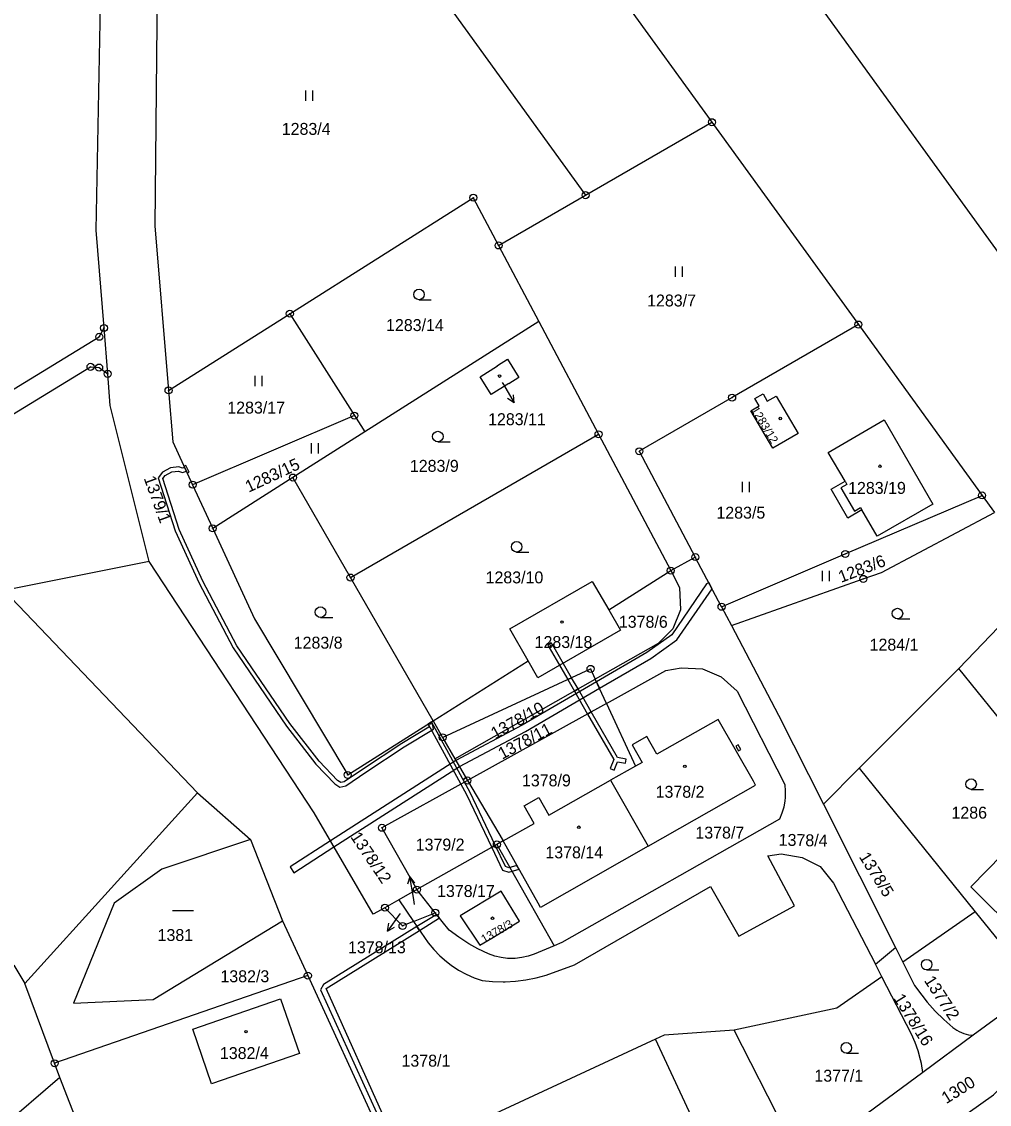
# Model space of a CAD drawing. Extents: x -562167 to -556918, y -1077891 to -1070763.
# Drawn here: x -559666.6 to -559528.9, y -1075327 to -1075172.9 of the extents above; entities that cross this region are included whole.
import ezdxf

# ---------------------------------------------------------------- set-up
doc = ezdxf.new("R2010")
doc.units = 0
for name, color, linetype in [('Hranice parcel', 7, 'Continuous'), ('Parcelní čísla', 7, 'Continuous'), ('Pop  PČ popisy', 7, 'Continuous'), ('Vnitřní kresba', 7, 'Continuous'), ('Věcná břemena k části', 7, 'Continuous'), ('Značky bodu BP', 7, 'Continuous'), ('Značky budov', 7, 'Continuous'), ('Značky kultur', 7, 'Continuous')]:
    doc.layers.add(name, color=color, linetype=linetype)

msp = doc.modelspace()

# ---------------------------------------------------------------- linework, layer by layer
at = {"layer": 'Hranice parcel'}
for p, q in [((-559616.74, -1075082.7), (-559508.88, -1075231.78)), ((-559633.14, -1075097.77), (-559568.42, -1075187.21)), ((-559648.43, -1075111.82), (-559586.39, -1075197.59)), ((-559586.39, -1075197.59), (-559568.42, -1075187.21)), ((-559568.42, -1075187.21), (-559547.57, -1075216)), ((-559598.77, -1075204.75), (-559586.39, -1075197.59)), ((-559598.77, -1075204.75), (-559593.03, -1075215.59)), ((-559645.74, -1075225.37), (-559628.48, -1075214.46)), ((-559628.48, -1075214.46), (-559619.3, -1075228.96)), ((-559654.4, -1075223.02), (-559654.92, -1075216.49)), ((-559593.03, -1075215.59), (-559617.83, -1075231.29)), ((-559593.03, -1075215.59), (-559584.55, -1075231.61)), ((-559547.57, -1075216), (-559529.98, -1075240.31)), ((-559619.3, -1075228.96), (-559642.32, -1075238.79)), ((-559619.3, -1075228.96), (-559617.83, -1075231.29)), ((-559617.83, -1075231.29), (-559628.04, -1075237.77)), ((-559619.85, -1075252), (-559584.55, -1075231.61)), ((-559584.55, -1075231.61), (-559574.28, -1075251.02)), ((-559628.04, -1075237.77), (-559639.45, -1075245)), ((-559619.85, -1075252), (-559628.04, -1075237.77)), ((-559642.32, -1075238.79), (-559639.45, -1075245)), ((-559529.98, -1075240.31), (-559528.22, -1075242.75)), ((-559574.28, -1075251.02), (-559570.78, -1075249.09)), ((-559567.05, -1075256.16), (-559570.78, -1075249.09)), ((-559608.09, -1075272.4), (-559619.85, -1075252)), ((-559583.1, -1075256.6), (-559574.28, -1075251.02)), ((-559567.05, -1075256.16), (-559565.65, -1075258.82)), ((-559533.28, -1075264.93), (-559526.49, -1075257.87)), ((-559608.09, -1075272.4), (-559594.56, -1075263.85)), ((-559547.45, -1075279.14), (-559533.28, -1075264.93)), ((-559508.11, -1075296.23), (-559533.28, -1075264.93)), ((-559604.99, -1075277.78), (-559585.01, -1075266.46)), ((-559583.41, -1075269.93), (-559585.01, -1075266.46)), ((-559583.41, -1075269.93), (-559603.21, -1075280.88)), ((-559583.41, -1075269.93), (-559579.3, -1075278.83)), ((-559608.09, -1075272.4), (-559606.74, -1075274.74)), ((-559606.74, -1075274.74), (-559604.99, -1075277.78)), ((-559604.99, -1075277.78), (-559603.21, -1075280.88)), ((-559579.3, -1075278.83), (-559582.85, -1075280.84)), ((-559552.55, -1075284.27), (-559547.45, -1075279.14)), ((-559547.45, -1075279.14), (-559530.96, -1075299.57)), ((-559603.21, -1075280.88), (-559598.14, -1075289.48)), ((-559582.85, -1075280.84), (-559577.5, -1075290.24)), ((-559666.17, -1075309.79), (-559641.62, -1075282.66)), ((-559641.62, -1075282.66), (-559634.09, -1075289.26)), ((-559552.55, -1075284.27), (-559542.31, -1075304.63)), ((-559558.82, -1075286.4), (-559589.78, -1075303.95)), ((-559634.09, -1075289.26), (-559629.52, -1075300.84)), ((-559598.14, -1075289.48), (-559599.02, -1075289.98)), ((-559599.02, -1075289.98), (-559610.4, -1075296.41)), ((-559599.02, -1075289.98), (-559590.88, -1075304.41)), ((-559551.1, -1075295.51), (-559545.15, -1075307.02)), ((-559610.4, -1075296.41), (-559612.98, -1075297.86)), ((-559607.78, -1075299.69), (-559610.4, -1075296.41)), ((-559612.98, -1075297.86), (-559614.95, -1075298.98)), ((-559612.98, -1075297.86), (-559610.88, -1075300.95)), ((-559610.88, -1075300.95), (-559607.78, -1075299.69)), ((-559605.79, -1075302.19), (-559607.78, -1075299.69)), ((-559530.96, -1075299.57), (-559541.25, -1075306.74)), ((-559530.96, -1075299.57), (-559522.17, -1075310.46)), ((-559629.52, -1075300.84), (-559625.92, -1075308.65)), ((-559610.88, -1075300.95), (-559608.8, -1075304)), ((-559590.88, -1075304.41), (-559593.7, -1075305.58)), ((-559589.78, -1075303.95), (-559590.88, -1075304.41)), ((-559545.15, -1075307.02), (-559542.31, -1075304.63)), ((-559542.31, -1075304.63), (-559541.25, -1075306.74)), ((-559667.76, -1075307.16), (-559666.17, -1075309.79)), ((-559544.22, -1075308.82), (-559545.15, -1075307.02)), ((-559541.25, -1075306.74), (-559539.57, -1075310.07)), ((-559625.92, -1075308.65), (-559661.95, -1075321.12)), ((-559625.92, -1075308.65), (-559615.78, -1075330.68)), ((-559540.01, -1075316.97), (-559544.22, -1075308.82)), ((-559661.95, -1075321.12), (-559666.17, -1075309.79)), ((-559522.17, -1075310.46), (-559531.22, -1075317.14)), ((-559555.67, -1075335.15), (-559565.25, -1075316.42)), ((-559531.22, -1075317.14), (-559538.42, -1075322.44)), ((-559661.19, -1075323.16), (-559661.95, -1075321.12)), ((-559661.19, -1075323.16), (-559677.66, -1075337.18)), ((-559656.31, -1075335.73), (-559661.19, -1075323.16)), ((-559538.42, -1075322.44), (-559555.67, -1075335.15))]:
    msp.add_line(p, q, dxfattribs=at)
for points in [[(-559649.72, -1075112.97), (-559646.94, -1075125.05), (-559647.7, -1075201.95), (-559645.74, -1075225.37)], [(-559654.92, -1075216.49), (-559656.04, -1075202.55), (-559654.55, -1075126.06), (-559654.77, -1075125.28)], [(-559628.48, -1075214.46), (-559602.37, -1075197.95), (-559598.77, -1075204.75)], [(-559696.59, -1075242.74), (-559683.29, -1075234.63), (-559686.52, -1075229.31), (-559685.67, -1075228.79), (-559682.43, -1075234.11), (-559655.59, -1075217.74), (-559654.92, -1075216.49)], [(-559547.57, -1075216), (-559565.54, -1075226.4), (-559578.75, -1075234.03), (-559570.78, -1075249.09)], [(-559597.3, -1075224.44), (-559597.34, -1075224.38), (-559599.82, -1075225.94), (-559601.39, -1075223.42), (-559598.91, -1075221.86), (-559598.94, -1075221.82), (-559597.51, -1075220.95), (-559595.89, -1075223.55), (-559597.3, -1075224.44)], [(-559702.63, -1075249.94), (-559656.84, -1075222.02), (-559655.62, -1075222.12), (-559654.4, -1075223.02)], [(-559648.52, -1075249.71), (-559654.04, -1075227.54), (-559654.4, -1075223.02)], [(-559645.74, -1075225.37), (-559645.13, -1075232.7), (-559642.32, -1075238.79)], [(-559556.13, -1075231.49), (-559559.75, -1075233.59), (-559562.86, -1075228.26), (-559561.71, -1075227.58), (-559562.31, -1075226.53), (-559561.13, -1075225.84), (-559560.54, -1075226.89), (-559559.26, -1075226.17), (-559556.13, -1075231.49)], [(-559551.88, -1075234.19), (-559543.93, -1075229.55), (-559536.97, -1075241.54), (-559544.88, -1075246.13), (-559547.08, -1075242.39), (-559549.06, -1075243.55), (-559551.45, -1075239.42), (-559549.48, -1075238.29), (-559551.88, -1075234.19)], [(-559567.05, -1075256.16), (-559549.45, -1075248.64), (-559529.98, -1075240.31)], [(-559565.65, -1075258.82), (-559546.88, -1075252.19), (-559544.27, -1075251.27), (-559528.22, -1075242.75)], [(-559639.45, -1075245), (-559633.51, -1075257.87), (-559620.24, -1075280.09), (-559608.09, -1075272.4)], [(-559648.52, -1075249.71), (-559669.15, -1075253.85), (-559641.62, -1075282.66)], [(-559614.95, -1075298.98), (-559616.6, -1075299.91), (-559625.03, -1075285.5), (-559648.52, -1075249.71)], [(-559574.28, -1075251.02), (-559573.01, -1075253.41), (-559572.91, -1075256.59), (-559573.97, -1075259.32), (-559576.07, -1075261.39), (-559585.01, -1075266.46)], [(-559594.56, -1075263.85), (-559597.16, -1075259.28), (-559585.44, -1075252.56), (-559583.1, -1075256.6)], [(-559583.1, -1075256.6), (-559581.42, -1075259.5), (-559593.18, -1075266.26), (-559594.56, -1075263.85)], [(-559565.65, -1075258.82), (-559558.93, -1075271.57), (-559552.55, -1075284.27)], [(-559583.41, -1075269.93), (-559574.96, -1075265.25), (-559572.78, -1075264.84), (-559569.75, -1075265), (-559567.1, -1075266.12), (-559564.81, -1075268.18), (-559558.06, -1075281.47)], [(-559606.74, -1075274.74), (-559585.69, -1075265), (-559585.01, -1075266.46)], [(-559577.5, -1075290.24), (-559562.2, -1075281.56), (-559562.52, -1075280.99), (-559567.55, -1075272.2), (-559576.27, -1075277.12), (-559577.68, -1075274.62), (-559579.77, -1075275.8), (-559578.35, -1075278.3), (-559579.3, -1075278.83)], [(-559603.21, -1075280.88), (-559615.37, -1075287.61), (-559610.4, -1075296.41)], [(-559598.14, -1075289.48), (-559593.71, -1075286.98), (-559595.12, -1075284.47), (-559593.04, -1075283.3), (-559591.62, -1075285.8), (-559582.85, -1075280.84)], [(-559558.06, -1075281.47), (-559557.98, -1075282.39), (-559557.99, -1075283.31), (-559558.04, -1075283.76), (-559558.2, -1075284.67), (-559558.46, -1075285.55), (-559558.82, -1075286.4)], [(-559520.98, -1075301.56), (-559518.66, -1075299.22), (-559519.76, -1075298.13), (-559515.5, -1075293.83), (-559522.6, -1075286.84), (-559531.58, -1075296), (-559524.56, -1075302.97), (-559522.08, -1075300.47), (-559520.98, -1075301.56)], [(-559634.09, -1075289.26), (-559646.7, -1075293.52), (-559653.49, -1075298.36), (-559659.26, -1075312.57), (-559647.94, -1075312.04), (-559629.52, -1075300.84)], [(-559577.5, -1075290.24), (-559592.8, -1075298.93), (-559593.12, -1075298.36), (-559598.14, -1075289.48)], [(-559592.02, -1075308.59), (-559587.98, -1075307.1), (-559568.64, -1075295.96), (-559564.58, -1075303.01), (-559556.66, -1075298.73), (-559560.48, -1075291.62), (-559558.58, -1075291.32), (-559555.58, -1075291.86), (-559553, -1075293.12), (-559551.1, -1075295.51)], [(-559598.41, -1075296.62), (-559604.23, -1075300.13), (-559601.45, -1075304.31), (-559599.76, -1075303.3), (-559595.8, -1075300.92), (-559598.41, -1075296.62)], [(-559610.88, -1075300.95), (-559612.44, -1075301.58), (-559614.95, -1075298.98)], [(-559593.7, -1075305.58), (-559594.58, -1075305.88), (-559595.48, -1075306.09), (-559596.41, -1075306.2), (-559596.57, -1075306.2), (-559597.5, -1075306.19), (-559598.42, -1075306.08), (-559599.32, -1075305.88), (-559600.2, -1075305.57), (-559601.72, -1075304.82), (-559602.99, -1075304.1), (-559604.42, -1075303.19), (-559605.79, -1075302.19)], [(-559608.8, -1075304), (-559608.01, -1075304.95), (-559607.14, -1075305.84), (-559606.21, -1075306.65), (-559605.52, -1075307.18), (-559604.48, -1075307.85), (-559603.39, -1075308.44), (-559602.26, -1075308.94), (-559601.09, -1075309.35), (-559599.62, -1075309.49), (-559598.14, -1075309.52), (-559597.84, -1075309.52), (-559596.37, -1075309.43), (-559594.9, -1075309.25), (-559593.45, -1075308.97), (-559592.02, -1075308.59)], [(-559544.22, -1075308.82), (-559550.65, -1075313.3), (-559565.25, -1075316.42)], [(-559539.57, -1075310.07), (-559538.57, -1075311.45), (-559537.77, -1075312.43), (-559536.63, -1075313.69), (-559535.42, -1075314.89), (-559534.14, -1075316.01), (-559533.58, -1075316.42), (-559533.22, -1075316.62), (-559532.58, -1075316.89), (-559531.91, -1075317.06), (-559531.22, -1075317.14)], [(-559629.79, -1075311.96), (-559627.1, -1075319.74), (-559639.61, -1075324.05), (-559642.28, -1075316.28), (-559629.79, -1075311.96)], [(-559565.25, -1075316.42), (-559575.21, -1075317.14), (-559576.45, -1075317.71)], [(-559538.42, -1075322.44), (-559538.61, -1075321.17), (-559538.73, -1075320.61), (-559539.06, -1075319.36), (-559539.49, -1075318.15), (-559540.01, -1075316.97)], [(-559576.45, -1075317.71), (-559599.82, -1075328.56), (-559593.33, -1075341.58)], [(-559593.33, -1075341.58), (-559570.36, -1075330.72), (-559576.45, -1075317.71)], [(-559541.96, -1075335.78), (-559535.54, -1075330.75), (-559528.37, -1075325.59), (-559524.01, -1075321.44), (-559519.9, -1075317.86)]]:
    msp.add_lwpolyline(points, dxfattribs=at)
at = {"layer": 'Pop  PČ popisy'}
for p, q in [((-559598.27, -1075224.24), (-559598.09, -1075224.55)), ((-559598.09, -1075224.55), (-559596.54, -1075227.12)), ((-559596.54, -1075227.12), (-559596.63, -1075226.01)), ((-559596.54, -1075227.12), (-559597.49, -1075226.52)), ((-559611.41, -1075294.57), (-559611.73, -1075295.65)), ((-559610.89, -1075297.53), (-559611.41, -1075294.57)), ((-559611.41, -1075294.57), (-559610.74, -1075295.47)), ((-559610.72, -1075298.53), (-559610.89, -1075297.53)), ((-559612.85, -1075299.84), (-559614.57, -1075302.3)), ((-559612.83, -1075299.81), (-559612.85, -1075299.84)), ((-559614.57, -1075302.3), (-559614.41, -1075301.19)), ((-559614.57, -1075302.3), (-559613.59, -1075301.77))]:
    msp.add_line(p, q, dxfattribs=at)
at = {"layer": 'Vnitřní kresba'}
for p, q in [((-559549.48, -1075238.29), (-559549.21, -1075238.75)), ((-559549.21, -1075238.75), (-559550.09, -1075239.25)), ((-559550.09, -1075239.25), (-559548.15, -1075242.56)), ((-559548.15, -1075242.56), (-559547.28, -1075242.05)), ((-559547.28, -1075242.05), (-559547.08, -1075242.39))]:
    msp.add_line(p, q, dxfattribs=at)
at = {"layer": 'Věcná břemena k části'}
for points in [[(-559643.2, -1075236.88), (-559643.45, -1075236.33), (-559643.74, -1075236.42), (-559644.27, -1075236.24), (-559645.44, -1075236.37), (-559646.62, -1075237), (-559647.22, -1075237.8), (-559644.81, -1075245.37), (-559641.38, -1075252.78), (-559636.56, -1075262), (-559628.97, -1075273.14), (-559624.77, -1075278.54), (-559622.06, -1075281.36), (-559621.36, -1075281.83), (-559620.53, -1075281.63), (-559617.68, -1075279.71), (-559612.21, -1075276.11), (-559608.02, -1075273.59), (-559608.19, -1075272.8), (-559608.77, -1075272.92), (-559608.7, -1075273.29), (-559612.53, -1075275.61), (-559618.02, -1075279.21), (-559620.77, -1075281.07), (-559621.24, -1075281.19), (-559621.68, -1075280.9), (-559624.31, -1075278.14), (-559628.49, -1075272.78), (-559636.04, -1075261.7), (-559640.84, -1075252.52), (-559644.25, -1075245.15), (-559646.56, -1075237.92), (-559646.22, -1075237.46), (-559645.26, -1075236.95), (-559644.33, -1075236.86), (-559643.74, -1075237.06)], [(-559643.53, -1075236.17), (-559643.45, -1075236.33), (-559643.2, -1075236.88), (-559643.09, -1075237.13), (-559642.81, -1075237.02), (-559643.28, -1075236.04)], [(-559574.12, -1075260.14), (-559577.66, -1075262.65), (-559584.83, -1075266.84), (-559584.41, -1075267.75), (-559577.11, -1075263.5), (-559573.39, -1075260.86), (-559568.4, -1075253.6), (-559568.87, -1075252.72), (-559569.17, -1075252.9)], [(-559591.57, -1075261.96), (-559591.32, -1075261.8), (-559591.53, -1075261.44), (-559591.79, -1075261.58)], [(-559588.94, -1075266.51), (-559588.4, -1075266.25), (-559591.06, -1075261.64), (-559591.32, -1075261.8), (-559591.57, -1075261.96)], [(-559591.53, -1075261.44), (-559591.32, -1075261.8), (-559591.06, -1075261.64), (-559591.27, -1075261.28)], [(-559587.99, -1075268.15), (-559587.47, -1075267.85), (-559588.4, -1075266.25), (-559588.94, -1075266.51)], [(-559622.2, -1075290.34), (-559604.35, -1075278.89), (-559594.95, -1075273.89), (-559584.41, -1075267.75), (-559584.83, -1075266.84), (-559595.43, -1075273.02), (-559604.85, -1075278.02), (-559622.7, -1075289.48), (-559628.44, -1075293.16), (-559627.91, -1075294)], [(-559586.1, -1075271.42), (-559585.58, -1075271.13), (-559587.47, -1075267.85), (-559587.99, -1075268.15)], [(-559603.36, -1075282.88), (-559599.76, -1075290.4), (-559599.24, -1075290.1), (-559602.82, -1075282.6), (-559608.31, -1075272.54), (-559608.82, -1075272.86)], [(-559581.84, -1075278.21), (-559580.71, -1075278.43), (-559580.6, -1075277.84), (-559581.84, -1075277.6), (-559585.58, -1075271.13), (-559586.1, -1075271.42), (-559582.36, -1075277.89), (-559582.88, -1075279.19), (-559582.32, -1075279.42)], [(-559564.29, -1075276.49), (-559564.67, -1075275.82), (-559565, -1075275.99), (-559564.63, -1075276.67)], [(-559599.24, -1075290.1), (-559599.76, -1075290.4), (-559598.21, -1075293.63), (-559597.31, -1075293.91), (-559595.87, -1075293.5), (-559596.17, -1075292.96), (-559597.31, -1075293.29), (-559597.79, -1075293.13)], [(-559607.18, -1075300.44), (-559607.58, -1075299.94), (-559610.39, -1075301.67), (-559610.02, -1075302.21)], [(-559623.68, -1075309.9), (-559624.11, -1075310.66), (-559615.15, -1075330.29), (-559615.78, -1075330.68), (-559615.52, -1075331.25), (-559614.73, -1075330.82), (-559614.44, -1075330.2), (-559623.33, -1075310.5), (-559610.02, -1075302.21), (-559610.39, -1075301.67)]]:
    msp.add_lwpolyline(points, close=True, dxfattribs=at)
at = {"layer": 'Značky bodu BP'}
for centre, radius in [((-559568.42, -1075187.21), 0.5), ((-559568.42, -1075187.21), 0.0303), ((-559586.39, -1075197.59), 0.5), ((-559602.37, -1075197.95), 0.5), ((-559602.37, -1075197.95), 0.0303), ((-559586.39, -1075197.59), 0.0303), ((-559598.77, -1075204.75), 0.5), ((-559598.77, -1075204.75), 0.0303), ((-559628.48, -1075214.46), 0.5), ((-559628.48, -1075214.46), 0.0303), ((-559547.57, -1075216), 0.5), ((-559654.92, -1075216.49), 0.5), ((-559654.92, -1075216.49), 0.0303), ((-559547.57, -1075216), 0.0303), ((-559655.59, -1075217.74), 0.5), ((-559655.59, -1075217.74), 0.0303), ((-559656.84, -1075222.02), 0.5), ((-559655.62, -1075222.12), 0.5), ((-559656.84, -1075222.02), 0.0303), ((-559655.62, -1075222.12), 0.0303), ((-559654.4, -1075223.02), 0.5), ((-559654.4, -1075223.02), 0.0303), ((-559645.74, -1075225.37), 0.5), ((-559645.74, -1075225.37), 0.0303), ((-559565.54, -1075226.4), 0.5), ((-559565.54, -1075226.4), 0.0303), ((-559619.3, -1075228.96), 0.5), ((-559619.3, -1075228.96), 0.0303), ((-559584.55, -1075231.61), 0.5), ((-559584.55, -1075231.61), 0.0303), ((-559578.75, -1075234.03), 0.5), ((-559578.75, -1075234.03), 0.0303), ((-559642.32, -1075238.79), 0.5), ((-559628.04, -1075237.77), 0.5), ((-559628.04, -1075237.77), 0.0303), ((-559642.32, -1075238.79), 0.0303), ((-559529.98, -1075240.31), 0.5), ((-559529.98, -1075240.31), 0.0303), ((-559639.45, -1075245), 0.5), ((-559639.45, -1075245), 0.0303), ((-559570.78, -1075249.09), 0.5), ((-559570.78, -1075249.09), 0.0303), ((-559549.45, -1075248.64), 0.5), ((-559549.45, -1075248.64), 0.0303), ((-559574.28, -1075251.02), 0.5), ((-559574.28, -1075251.02), 0.0303), ((-559619.85, -1075252), 0.5), ((-559619.85, -1075252), 0.0303), ((-559546.88, -1075252.19), 0.5), ((-559546.88, -1075252.19), 0.0303), ((-559567.05, -1075256.16), 0.5), ((-559567.05, -1075256.16), 0.0303), ((-559585.69, -1075265), 0.5), ((-559585.69, -1075265), 0.0303), ((-559606.74, -1075274.74), 0.5), ((-559606.74, -1075274.74), 0.0303), ((-559620.24, -1075280.09), 0.5), ((-559620.24, -1075280.09), 0.0303), ((-559603.21, -1075280.88), 0.5), ((-559603.21, -1075280.88), 0.0303), ((-559615.37, -1075287.61), 0.5), ((-559615.37, -1075287.61), 0.0303), ((-559599.02, -1075289.98), 0.5), ((-559599.02, -1075289.98), 0.0303), ((-559610.4, -1075296.41), 0.5), ((-559610.4, -1075296.41), 0.0303), ((-559614.95, -1075298.98), 0.5), ((-559614.95, -1075298.98), 0.0303), ((-559607.78, -1075299.69), 0.5), ((-559607.78, -1075299.69), 0.0303), ((-559612.44, -1075301.58), 0.5), ((-559612.44, -1075301.58), 0.0303), ((-559625.92, -1075308.65), 0.5), ((-559625.92, -1075308.65), 0.0303), ((-559661.95, -1075321.12), 0.5), ((-559661.95, -1075321.12), 0.0303)]:
    msp.add_circle(centre, radius, dxfattribs=at)
at = {"layer": 'Značky budov'}
for centre in [(-559598.64, -1075223.34), (-559558.69, -1075229.37), (-559544.51, -1075236.16), (-559589.75, -1075258.34), (-559572.27, -1075278.86), (-559587.36, -1075287.53), (-559599.64, -1075300.48), (-559634.71, -1075316.62)]:
    msp.add_circle(centre, 0.175, dxfattribs=at)
at = {"layer": 'Značky kultur'}
for p, q in [((-559626.19, -1075184.19), (-559626.19, -1075182.69)), ((-559625.19, -1075184.19), (-559625.19, -1075182.69)), ((-559573.62, -1075209.23), (-559573.62, -1075207.73)), ((-559572.62, -1075209.23), (-559572.62, -1075207.73)), ((-559610.1, -1075212.47), (-559608.35, -1075212.47)), ((-559633.41, -1075224.78), (-559633.41, -1075223.28)), ((-559632.41, -1075224.78), (-559632.41, -1075223.28)), ((-559625.39, -1075234.36), (-559625.39, -1075232.86)), ((-559624.39, -1075234.36), (-559624.39, -1075232.86)), ((-559607.42, -1075232.69), (-559605.67, -1075232.69)), ((-559564.09, -1075239.86), (-559564.09, -1075238.36)), ((-559563.09, -1075239.86), (-559563.09, -1075238.36)), ((-559596.21, -1075248.37), (-559594.46, -1075248.37)), ((-559552.7, -1075252.53), (-559552.7, -1075251.03)), ((-559551.7, -1075252.53), (-559551.7, -1075251.03)), ((-559624.12, -1075257.68), (-559622.37, -1075257.68)), ((-559542.02, -1075257.88), (-559540.27, -1075257.88)), ((-559531.54, -1075282.15), (-559529.79, -1075282.15)), ((-559645.2, -1075299.36), (-559642.2, -1075299.36)), ((-559537.86, -1075307.83), (-559536.11, -1075307.83)), ((-559549.29, -1075319.67), (-559547.54, -1075319.67))]:
    msp.add_line(p, q, dxfattribs=at)
for centre in [(-559610.1, -1075211.72), (-559607.42, -1075231.94), (-559596.21, -1075247.62), (-559624.12, -1075256.93), (-559542.02, -1075257.13), (-559531.54, -1075281.4), (-559537.86, -1075307.08), (-559549.29, -1075318.92)]:
    msp.add_circle(centre, 0.75, dxfattribs=at)

# ---------------------------------------------------------------- texts
at = {"layer": 'Parcelní čísla'}
for s, p in [('1283/4', (-559629.63, -1075189.01)), ('1283/7', (-559577.64, -1075213.43)), ('1283/14', (-559614.79, -1075216.93)), ('1283/17', (-559637.38, -1075228.67)), ('1283/11', (-559600.27, -1075230.32)), ('1283/9', (-559611.4, -1075236.96)), ('1283/19', (-559549.04, -1075240.1)), ('1283/5', (-559567.78, -1075243.62)), ('1283/10', (-559600.63, -1075252.83)), ('1378/6', (-559581.66, -1075259.15)), ('1283/18', (-559593.65, -1075262.03)), ('1283/8', (-559627.93, -1075262.12)), ('1284/1', (-559545.98, -1075262.4)), ('1378/9', (-559595.45, -1075281.72)), ('1378/2', (-559576.43, -1075283.34)), ('1286', (-559534.33, -1075286.31)), ('1378/7', (-559570.77, -1075289.15)), ('1379/2', (-559610.57, -1075290.85)), ('1378/14', (-559592.12, -1075291.96)), ('1378/17', (-559607.53, -1075297.46)), ('1381', (-559647.3, -1075303.72)), ('1378/13', (-559620.2, -1075305.46)), ('1382/3', (-559638.36, -1075309.59)), ('1382/4', (-559638.43, -1075320.52)), ('1378/1', (-559612.59, -1075321.6)), ('1377/1', (-559553.84, -1075323.74))]:
    msp.add_text(s, height=1.7, dxfattribs=at).set_placement(p)
for s, height, rotation, p in [('1283/12', 1.19, 301, (-559562.89, -1075228.13)), ('1283/15', 1.7, 25, (-559634.34, -1075239.94)), ('1379/1', 1.7, 290, (-559649.29, -1075237.88)), ('1283/6', 1.7, 21, (-559550.03, -1075252.77)), ('1378/10', 1.7, 29, (-559599.28, -1075275.05)), ('1378/11', 1.7, 28, (-559598.27, -1075277.93)), ('1378/12', 1.7, 304, (-559619.92, -1075288.9)), ('1378/4', 1.7, 359, (-559558.93, -1075290.16)), ('1378/5', 1.7, 302, (-559547.55, -1075291.73)), ('1378/3', 1.19, 30, (-559600.84, -1075304.07)), ('1377/2', 1.7, 303, (-559538.29, -1075309.34)), ('1378/16', 1.7, 302, (-559542.64, -1075311.87)), ('1300', 1.7, 32, (-559535.07, -1075326.95))]:
    msp.add_text(s, height=height, rotation=rotation, dxfattribs=at).set_placement(p)

doc.saveas('drawing.dxf')
